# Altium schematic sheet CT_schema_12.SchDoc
size 274 x 160 mm
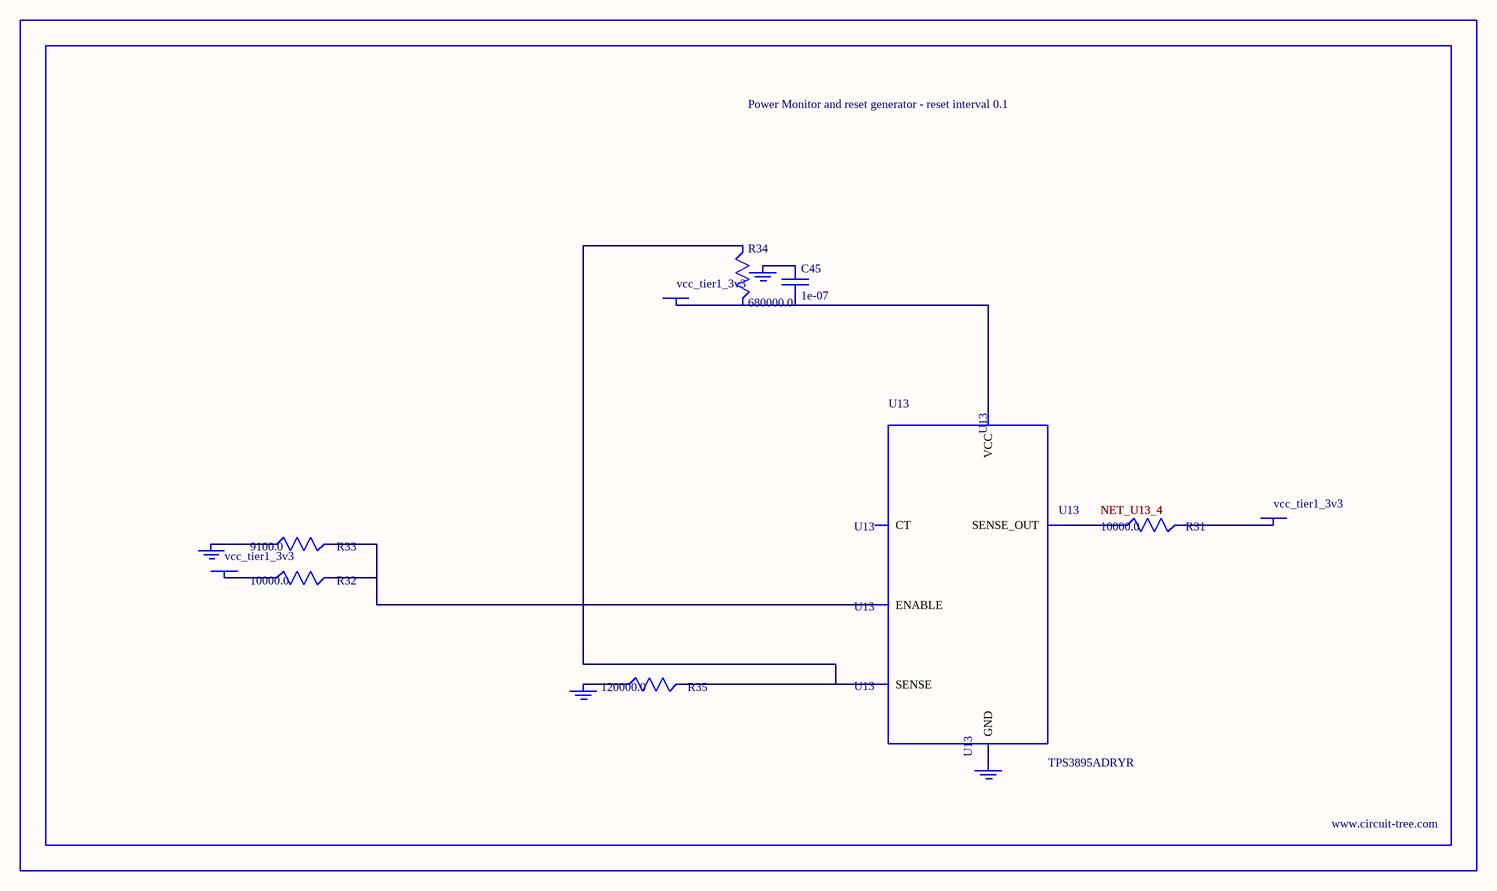
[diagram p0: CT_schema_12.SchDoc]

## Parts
BORDER11  (no value)
C45  1e-07  [C0402]
GND_INSTANCE_11_0  (no value)
GND_INSTANCE_11_1  (no value)
GND_INSTANCE_11_2  (no value)
GND_INSTANCE_11_3  (no value)
POWER_INSTANCE_11_0  vcc_tier1_3v3
POWER_INSTANCE_11_1  vcc_tier1_3v3
POWER_INSTANCE_11_2  vcc_tier1_3v3
R31  10000.0  [R0603]
R32  10000.0  [R0603]
R33  9100.0  [R0603]
R34  680000.0  [R0603]
R35  120000.0  [R0603]
U13  TPS3895ADRYR  [SON-6]

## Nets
NetC45_1: C45.1 GND_INSTANCE_11_2.0(GND)
NetC45_2: C45.2 POWER_INSTANCE_11_2.0(PWR) R34.2 U13.6(VCC)
NetGND_INSTANCE_11_0_0: GND_INSTANCE_11_0.0(GND) R33.1
NetGND_INSTANCE_11_1_0: GND_INSTANCE_11_1.0(GND) R35.1
NetGND_INSTANCE_11_3_0: GND_INSTANCE_11_3.0(GND) U13.2(GND)
NetPOWER_INSTANCE_11_0_0: POWER_INSTANCE_11_0.0(PWR) R32.1
NetPOWER_INSTANCE_11_1_0: POWER_INSTANCE_11_1.0(PWR) R31.2
NetR31_1: R31.1 U13.4(SENSE_OUT)
NetR32_2: R32.2 R33.2 U13.1(ENABLE)
NetR34_1: R34.1 R35.2 U13.3(SENSE)

Not connected (* = marked no-connect by the designer): U13 5(CT)

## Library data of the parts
BORDER11 = BORDER_PAGE11
C45 = C0402C104K3RACTU
GND_INSTANCE_11_0-GND_INSTANCE_11_3 = GND
POWER_INSTANCE_11_0-POWER_INSTANCE_11_2 = PWR
R31 R32 = RC0603JR-0710KL
R33 = RC0603JR-079K1L
R34 = RC0603JR-07680KL
R35 = RC0603JR-07120KL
